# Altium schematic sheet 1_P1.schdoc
size 307 x 218 mm; Symbol: Sheet-Symbol_A4; Device: Sheet-Symbol_A4; Company: 嘉立创EDA; Version: V1.0; Page Size: A4; @Project Name: 电子宠物小呆; @Page Count: 1; @Update Date: 2025-02-11; @Create Date: 2025-02-11; @Schematic Name: 电子宠物小呆; @Page No: 1; @Page Name: P1; @Board Name: Board_qzf; @Create Time: 08:38:01; @Update Time: 19:49:19; Width: 1170; Height: 825; Region Start: 1; X Region Count: 6; Y Region Count: 4; Blade Width: 10; Title Block Position: 3
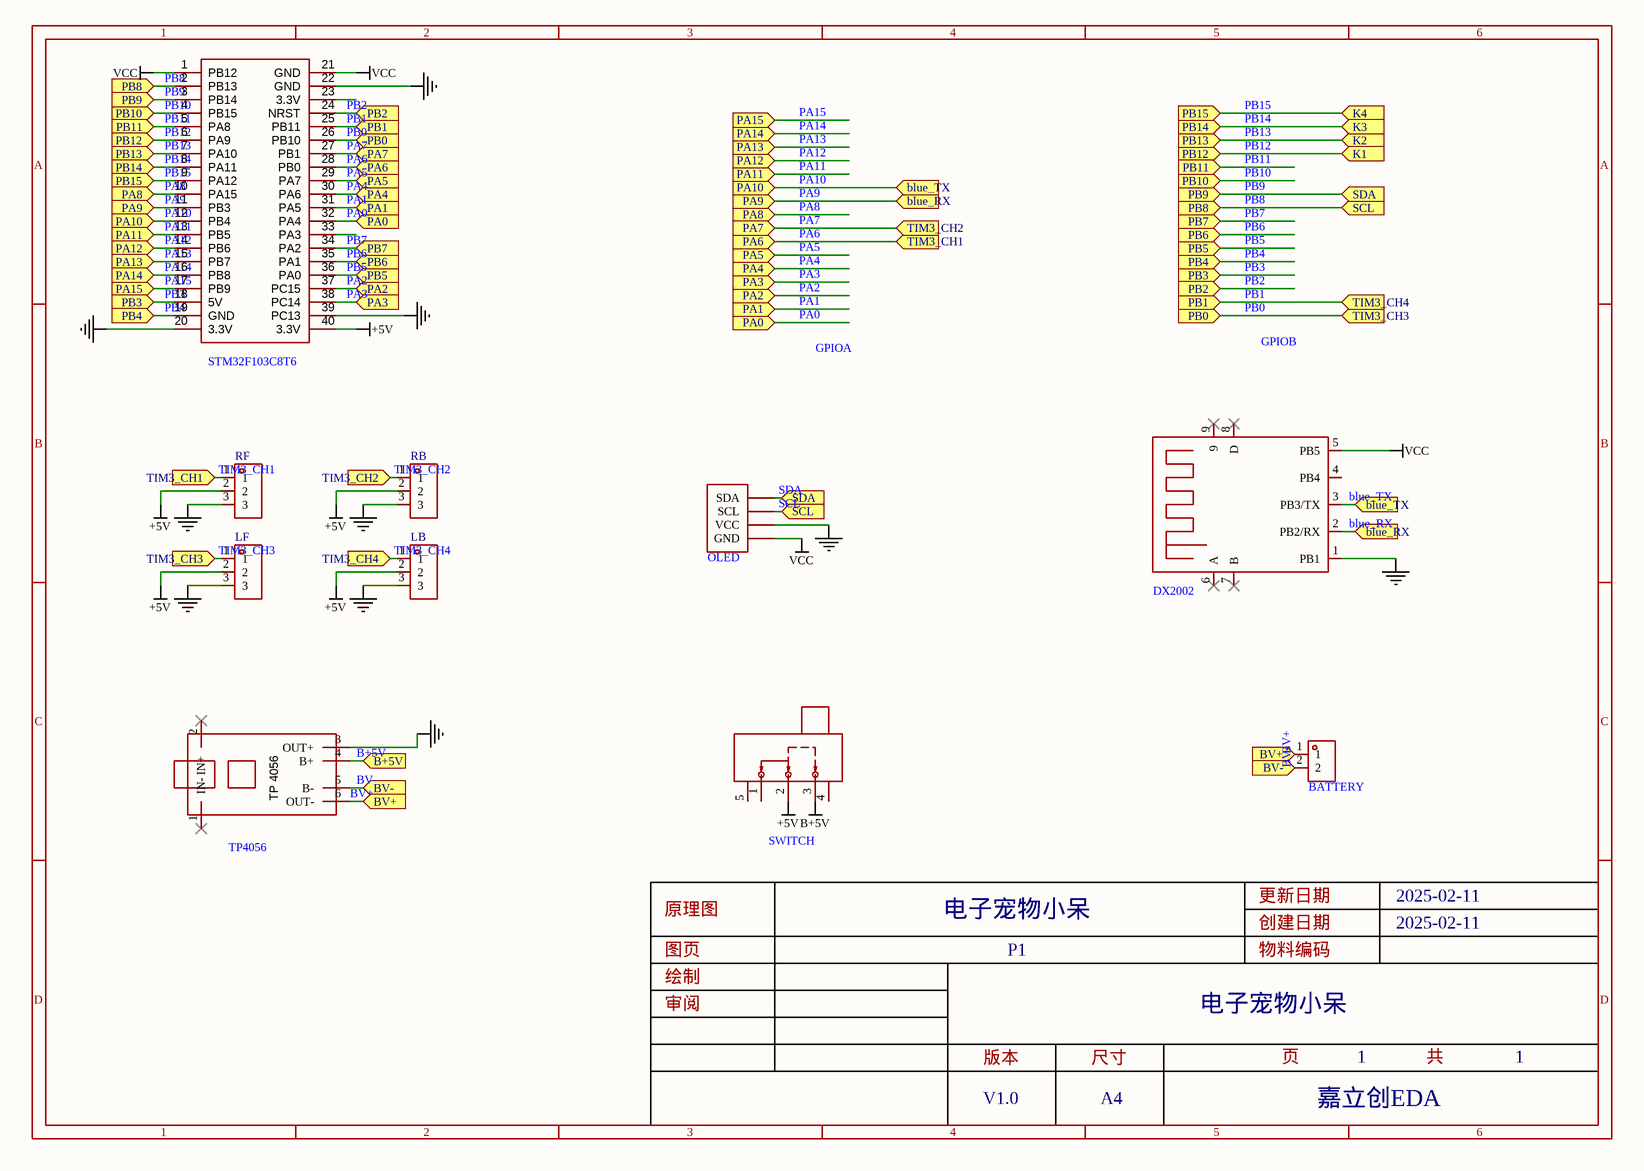
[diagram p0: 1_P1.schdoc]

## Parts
H1  BATTERY  [HDR-TH_2P-P2.54-V-M]
LB  3pin插件排针  [HDR-TH_3P-P2.54-V-M]  (value not drawn)
LF  3pin插件排针  [HDR-TH_3P-P2.54-V-M]  (value not drawn)
OLED1.3寸  OLED  [oled 1.3寸]
RB  3pin插件排针  [HDR-TH_3P-P2.54-V-M]  (value not drawn)
RF  3pin插件排针  [HDR-TH_3P-P2.54-V-M]  (value not drawn)
STM32F103C8T6  (no value)  [STM32F103C8T6]
TP4056  (no value)  [TP4056模块]
U7  SWITCH  [SW-TH_SS-12F44-G5_C2998807]
U9  DX2002  [realdx2002]

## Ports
B+5V (in), blue_RX (in), blue_TX (in), BV+ (in), BV- (in), K1 (in), K2 (in), K3 (in), K4 (in), PA0 (in), PA1 (in), PA2 (in), PA3 (in), PA4 (in), PA5 (in), PA6 (in), PA7 (in), PA8 (in), PA9 (in), PA10 (in), PA11 (in), PA12 (in), PA13 (in), PA14 (in), PA15 (in), PB0 (in), PB1 (in), PB2 (in), PB3 (in), PB4 (in), PB5 (in), PB6 (in), PB7 (in), PB8 (in), PB9 (in), PB10 (in), PB11 (in), PB12 (in), PB13 (in), PB14 (in), PB15 (in), SCL (in), SDA (in), TIM3_CH1 (in), TIM3_CH2 (in), TIM3_CH3 (in), TIM3_CH4 (in)

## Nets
+5V: LB.2 LF.2 RB.2 RF.2 STM32F103C8T6.40(3.3V) U7.2
B+5V: TP4056.4(B+) U7.3 ; port B+5V
GND: LB.3 LF.3 OLED1.3寸.2(VCC) RB.3 RF.3 STM32F103C8T6.20(3.3V) STM32F103C8T6.22(GND) STM32F103C8T6.39(PC13) TP4056.3(OUT+) U9.1(PB1)
VCC: OLED1.3寸.1(GND) STM32F103C8T6.1(PB12) STM32F103C8T6.21(GND) U9.5(PB5)
blue_RX: STM32F103C8T6.11(PB3) U9.2(PB2/RX) ; port PA9, port blue_RX  [also labelled PA9]
blue_TX: STM32F103C8T6.12(PB4) U9.3(PB3/TX) ; port PA10, port blue_TX  [also labelled PA10]
BV+: H1.1 TP4056.6(OUT-) ; port BV+
BV-: H1.2 TP4056.5(B-) ; port BV-
PA0: STM32F103C8T6.32(PA4) ; port PA0
PA1: STM32F103C8T6.31(PA5) ; port PA1
PA2: STM32F103C8T6.37(PC15) ; port PA2
PA3: STM32F103C8T6.38(PC14) ; port PA3
PA4: STM32F103C8T6.30(PA6) ; port PA4
PA5: STM32F103C8T6.29(PA7) ; port PA5
PA6: RF.1 STM32F103C8T6.28(PB0) ; port PA6, port TIM3_CH1  [also labelled TIM3_CH1]
PA7: RB.1 STM32F103C8T6.27(PB1) ; port PA7, port TIM3_CH2  [also labelled TIM3_CH2]
PA8: STM32F103C8T6.10(PA15) ; port PA8
PA11: STM32F103C8T6.13(PB5) ; port PA11
PA12: STM32F103C8T6.14(PB6) ; port PA12
PA13: STM32F103C8T6.15(PB7) ; port PA13
PA14: STM32F103C8T6.16(PB8) ; port PA14
PA15: STM32F103C8T6.17(PB9) ; port PA15
PB0: LF.1 STM32F103C8T6.26(PB10) ; port PB0, port TIM3_CH3  [also labelled TIM3_CH3]
PB1: LB.1 STM32F103C8T6.25(PB11) ; port PB1, port TIM3_CH4  [also labelled TIM3_CH4]
PB2: STM32F103C8T6.24(NRST) ; port PB2
PB3: STM32F103C8T6.18(5V) ; port PB3
PB4: STM32F103C8T6.19(GND) ; port PB4
PB5: STM32F103C8T6.36(PA0) ; port PB5
PB6: STM32F103C8T6.35(PA1) ; port PB6
PB7: STM32F103C8T6.34(PA2) ; port PB7
PB8: OLED1.3寸.3(SCL) STM32F103C8T6.2(PB13) ; port PB8, port SCL  [also labelled SCL]
PB9: OLED1.3寸.4(SDA) STM32F103C8T6.3(PB14) ; port PB9, port SDA  [also labelled SDA]
PB10: STM32F103C8T6.4(PB15) ; port PB10
PB11: STM32F103C8T6.5(PA8) ; port PB11
PB12: STM32F103C8T6.6(PA9) ; port PB12, port K1
PB13: STM32F103C8T6.7(PA10) ; port PB13, port K2
PB14: STM32F103C8T6.8(PA11) ; port PB14, port K3
PB15: STM32F103C8T6.9(PA12) ; port PB15, port K4

Not connected (* = marked no-connect by the designer): STM32F103C8T6 23(3.3V) 33(PA3); TP4056 1(IN-)* 2(IN+)*; U7 1 4 5; U9 4(PB4) 6(A)* 7(B)* 8(D)* 9*

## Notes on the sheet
- GPIOA
- GPIOB

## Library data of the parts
H1 = PZ254V-11-02P: Manufacturer: XFCN(兴飞); Add into BOM: yes; Pin Structure: 1x2P; Pitch: 2.54mm; Circluar Pins/Square Pins: 方针
LB LF RB RF = 3pin插件排针: Add into BOM: yes
OLED1.3寸 = OLED 4PIN: Add into BOM: yes; _: 3
STM32F103C8T6 = STM32F103C8T6最小系统: Add into BOM: yes
TP4056 = TP4056模块: Add into BOM: yes
U7 = SS-12F44-G5: Manufacturer: DEALON(德艺隆); Symbol: SS-12F44-G5_C2998807; Add into BOM: yes; Circuit: 单刀双掷; Actuator Color: 黑色; Actuator Style: 矩形柱状; Pin Style: PC引脚; Switch Length: 12.2mm; Switch Width: 5.9mm; Switch Height: 11mm
U9 = DX2002: Add into BOM: yes; PinNumber: U9(6,7,8,9)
